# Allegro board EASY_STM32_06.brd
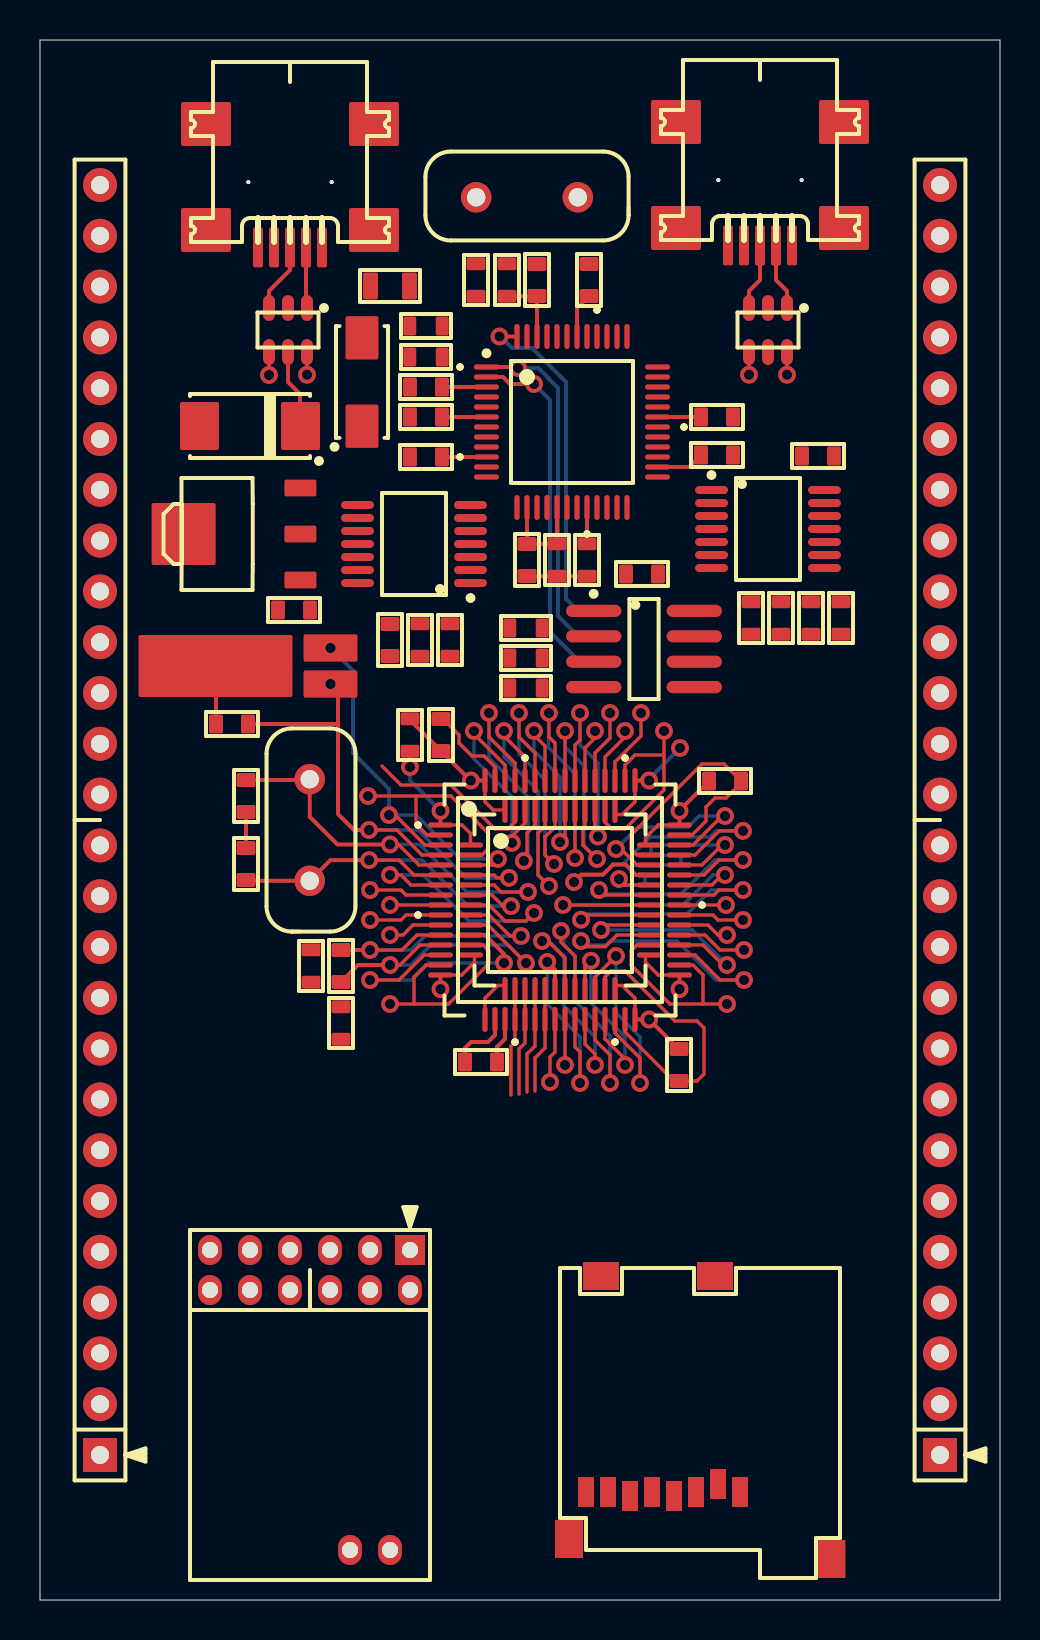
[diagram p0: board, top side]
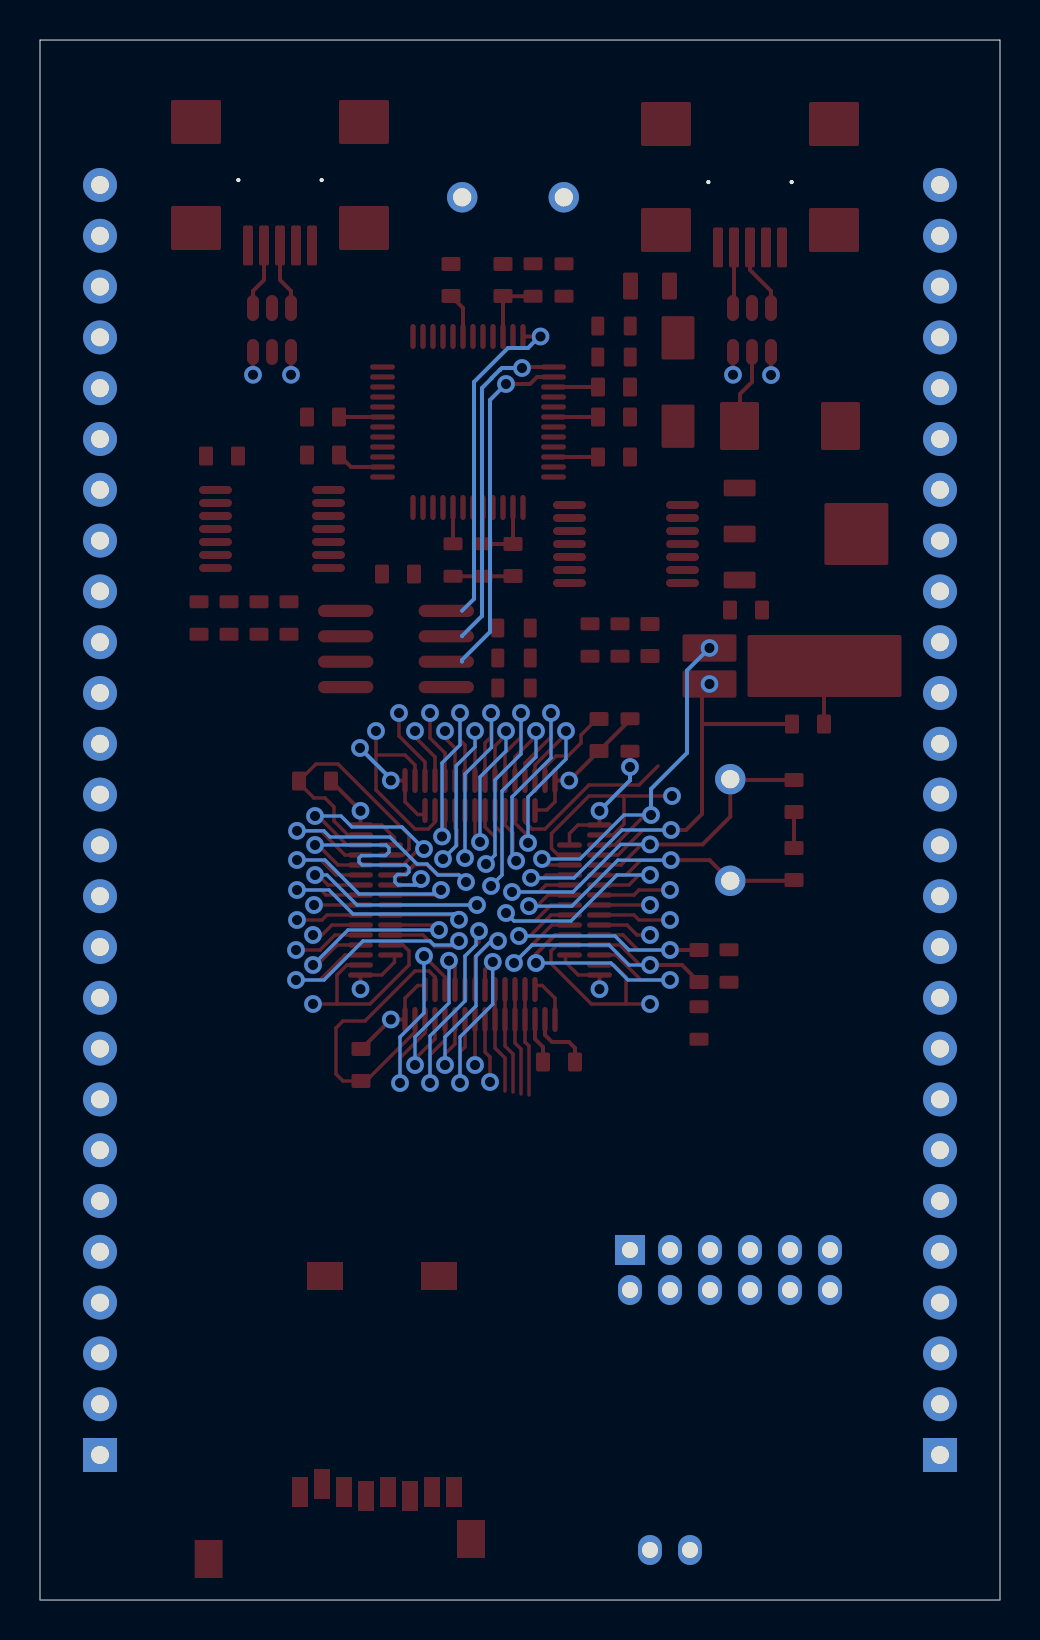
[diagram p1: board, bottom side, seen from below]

Outline 48 x 78 mm; copper layers: TOP, BOTTOM. Coordinates in mm from the lower left corner of the outline.
Outline path: 0,78 0,0 48,0 48,78 0,78

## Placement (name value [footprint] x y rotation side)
C1  22pF  [CAP0603_B]  10.3 40.2 270 top
C2  22p  [CAP0603_B]  10.3 36.8 90 top
C3  15p  [CAP0603_B]  9.6 43.8 180 top
C4  15p  [CAP0603_B]  12.7 49.5 180 top
C5  100n  [CAP0603_B]  15.05 31.7 90 top
C6  100n  [CAP0603_B]  31.95 26.75 270 top
C7  100n  [CAP0603_B]  34.25 40.95 0 top
C8  100n  [CAP0603_B]  20.05 43.25 90 top
C9  100n  [CAP0603_B]  22.05 26.9 180 top
C11  100n  [CAP0603_B]  19.3 60.65 180 top
C12  100n  [CAP0603_B]  27.45 66 90 top
C14  100n  [CAP0603_B]  19.3 57.15 180 top
C15  100n  [CAP0603_B]  24.35 52 270 top
C16  100n  [CAP0603_B]  33.85 57.25 0 top
C17  100n  [CAP0603_B]  33.85 59.15 0 top
C18  100n  [CAP0603_B]  24.85 66 90 top
C19  100n  [CAP0603_B]  19.3 59.15 180 top
C22  100n  [CAP0603_B]  30.1 51.3 180 top
C23  220uF  [CAP220UF]  10.5 58.7 180 top
C45  100nF  [CAP0603_B]  38.9 57.2 180 top
C46  100nF  [CAP0603_B]  17.5 48 270 top
D2  1N5819  [SS14]  16.1 60.9 90 top
J1  USB_MB  [HIROSE-US60-MB-5ST]  12.5 76.9 180 top
J2  USB_MB  [HIROSE-US60-MB-5ST]  36 77 180 top
L1  FB60R  [RES0805_B]  17.5 65.7 180 top
NOREF  -  [#3]  50 0 90 top
NOREF#2  -  [#3]  0 -2 0 top
R1  0R  [RES0603_B]  18.5 43.25 90 top
R2  0R  [RES0603_B]  15.05 28.85 270 top
R3  0R  [RES0603_B]  13.55 31.7 270 top
R4  470R  [RES0603_B]  23.35 66 270 top
R5  4K7  [RES0603_B]  19.3 63.7 0 top
R6  10K  [RES0603_B]  19.3 62.15 180 top
R7  10K  [RES0603_B]  27.35 52 270 top
R8  10K  [RES0603_B]  24.3 45.6 0 top
R9  10K  [RES0603_B]  24.3 47.1 0 top
R10  10K  [RES0603_B]  24.3 48.6 0 top
R13  1K5  [RES0603_B]  21.8 66 90 top
R14  100K  [RES0603_B]  25.85 52 270 top
R35  100R  [RES0603_B]  35.55 49.1 270 top
R36  100R  [RES0603_B]  40.05 49.1 270 top
R37  100R  [RES0603_B]  37.05 49.1 270 top
R38  100R  [RES0603_B]  38.55 49.1 270 top
R39  100K  [RES0603_B]  19 48 90 top
R40  100K  [RES0603_B]  20.5 48 90 top
REF  val  [unnamed]  18.5 17.5 180 top
REF#2  val  [unnamed#2]  45 7.25 90 top
U1  STM32F103RCT6  [LQFP64_MODIFIED]  26 35 0 top
U2  STM32F100  [LQFP48L_MODIFIED]  26 35 0 top
U3  FT2232D  [LQFP48L]  26.6 58.9 0 top
U4  AT93C46-10SI-2.7  [SOIC8S1JEDECM]  30.2 47.55 270 top
U5  74LVC125A  [TSOP65P640X120-14]  36.4 53.55 270 top
U6  74LVC125A  [TSOP65P640X120-14]  18.7 52.8 90 top
U7  LD1117-3V3  [SOT-223]  9.82 53.3 90 top
U10  MICRO_SD  [MICRO_SD_PUSH]  40 16.6 180 top
U11  USBLC6-2P6  [SOT23-6L]  36.4 63.5 180 top
U12  USBLC6-2P6  [SOT23-6L]  12.4 63.5 180 top
UNK*  val  [unnamed#2]  3 7.25 90 top
Y1  8M  [XTAL_DIP]  13.49 35.96 90 top
Y2  32.768KHz  [RTC-CRYSTAL]  10.53 46.7 90 top
Y3  6M  [XTAL_DIP]  26.89 70.14 180 top

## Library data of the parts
C1-C9 = C1005_0: User Part Number: pn; Tolerance: RichardLC
C11 C12 C14-C19 C22 = CAP NP_0: User Part Number: pn; Tolerance: RichardLC
C23 = CAPACITOR POL: User Part Number: pn; Tolerance: RichardLC
C45 C46 = C1005_5: User Part Number: pn; Tolerance: RichardLC
D2 = DIODE SCHOTTKY_1: User Part Number: pn; Tolerance: RichardLC
J1 J2 = CON9_2: User Part Number: pn; Tolerance: RichardLC
L1 = INDUCTOR/SM_0: User Part Number: pn; Tolerance: RichardLC
R1-R10 R13 R14 R35-R40 = R_0: User Part Number: pn; Tolerance: RichardLC
REF REF#2 = -: User Part Number: pn; Tolerance: RichardLC
U1 = STM32F103RCT6_2: User Part Number: pn; Tolerance: RichardLC
U2 = STM32F100_1: User Part Number: pn; Tolerance: RichardLC
U3 = FT2232D_0: User Part Number: pn; Tolerance: RichardLC
U4 = 93C46_2: User Part Number: pn; Tolerance: RichardLC
U5 U6 = 74HC125/LCC_0: User Part Number: pn; Tolerance: RichardLC
U7 = LD1117: User Part Number: pn; Tolerance: RichardLC
U10 = MOLEX_uSD_0: User Part Number: pn; Tolerance: RichardLC
U11 U12 = USBLC6-2P6: User Part Number: pn; Tolerance: RichardLC
UNK* = -: Tolerance: RichardLC; User Part Number: pn
Y1 Y3 = ZTB: Tolerance: ***; User Part Number: ***
Y2 = ZTA_0: User Part Number: pn; Tolerance: RichardLC

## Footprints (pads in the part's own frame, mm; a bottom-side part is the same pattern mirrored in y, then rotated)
CAP220UF
  custom 0.487x0.487 smd: 1(-2.525,0) 2(2.525,0)
CAP0603_B
  custom 0.175x0.175 smd: 1(-0.8,0) 2(0.8,0)
HIROSE-US60-MB-5ST
  round 0.2 hole 0.9 unplated: (-2.083,6.005) (2.083,6.005)
  custom 0.125x0.125 smd: 1(-1.6,9.271) 2(-0.8,9.271) 3(0,9.271) 4(0.8,9.271) 5(1.6,9.271)
  custom 0.55x0.55 smd: 6(-4.2,3.1) 7(4.2,3.1) 8(-4.2,8.4) 9(4.2,8.4)
LQFP48L
  oval 1.25x0.27 smd: 1(-4.275,2.75) 2(-4.275,2.25) 3(-4.275,1.75) 4(-4.275,1.25) 5(-4.275,0.75) 6(-4.275,0.25) 7(-4.275,-0.25) 8(-4.275,-0.75) 9(-4.275,-1.25) 10(-4.275,-1.75) 11(-4.275,-2.25) 12(-4.275,-2.75) 25(4.275,-2.75) 26(4.275,-2.25) 27(4.275,-1.75) 28(4.275,-1.25) 29(4.275,-0.75) 30(4.275,-0.25) 31(4.275,0.25) 32(4.275,0.75) 33(4.275,1.25) 34(4.275,1.75) 35(4.275,2.25) 36(4.275,2.75)
  oval 0.27x1.25 smd: 13(-2.75,-4.275) 14(-2.25,-4.275) 15(-1.75,-4.275) 16(-1.25,-4.275) 17(-0.75,-4.275) 18(-0.25,-4.275) 19(0.25,-4.275) 20(0.75,-4.275) 21(1.25,-4.275) 22(1.75,-4.275) 23(2.25,-4.275) 24(2.75,-4.275) 37(2.75,4.275) 38(2.25,4.275) 39(1.75,4.275) 40(1.25,4.275) 41(0.75,4.275) 42(0.25,4.275) 43(-0.25,4.275) 44(-0.75,4.275) 45(-1.25,4.275) 46(-1.75,4.275) 47(-2.25,4.275) 48(-2.75,4.275)
LQFP48L_MODIFIED
  oval 1.25x0.27 smd: 1(-4.475,2.75) 2(-4.475,2.25) 3(-4.475,1.75) 4(-4.475,1.25) 5(-4.475,0.75) 6(-4.475,0.25) 7(-4.475,-0.25) 8(-4.475,-0.75) 9(-4.475,-1.25) 10(-4.475,-1.75) 11(-4.475,-2.25) 12(-4.475,-2.75) 25(4.475,-2.75) 26(4.475,-2.25) 27(4.475,-1.75) 28(4.475,-1.25) 29(4.475,-0.75) 30(4.475,-0.25) 31(4.475,0.25) 32(4.475,0.75) 33(4.475,1.25) 34(4.475,1.75) 35(4.475,2.25) 36(4.475,2.75)
  oval 0.27x1.25 smd: 13(-2.75,-4.475) 14(-2.25,-4.475) 15(-1.75,-4.475) 16(-1.25,-4.475) 17(-0.75,-4.475) 18(-0.25,-4.475) 19(0.25,-4.475) 20(0.75,-4.475) 21(1.25,-4.475) 22(1.75,-4.475) 23(2.25,-4.475) 24(2.75,-4.475) 37(2.75,4.475) 38(2.25,4.475) 39(1.75,4.475) 40(1.25,4.475) 41(0.75,4.475) 42(0.25,4.475) 43(-0.25,4.475) 44(-0.75,4.475) 45(-1.25,4.475) 46(-1.75,4.475) 47(-2.25,4.475) 48(-2.75,4.475)
LQFP64_MODIFIED
  oval 1.25x0.27 smd: 1(-5.975,3.75) 2(-5.975,3.25) 3(-5.975,2.75) 4(-5.975,2.25) 5(-5.975,1.75) 6(-5.975,1.25) 7(-5.975,0.75) 8(-5.975,0.25) 9(-5.975,-0.25) 10(-5.975,-0.75) 11(-5.975,-1.25) 12(-5.975,-1.75) 13(-5.975,-2.25) 14(-5.975,-2.75) 15(-5.975,-3.25) 16(-5.975,-3.75) 33(5.975,-3.75) 34(5.975,-3.25) 35(5.975,-2.75) 36(5.975,-2.25) 37(5.975,-1.75) 38(5.975,-1.25) 39(5.975,-0.75) 40(5.975,-0.25) 41(5.975,0.25) 42(5.975,0.75) 43(5.975,1.25) 44(5.975,1.75) 45(5.975,2.25) 46(5.975,2.75) 47(5.975,3.25) 48(5.975,3.75)
  oval 0.27x1.25 smd: 17(-3.75,-5.975) 18(-3.25,-5.975) 19(-2.75,-5.975) 20(-2.25,-5.975) 21(-1.75,-5.975) 22(-1.25,-5.975) 23(-0.75,-5.975) 24(-0.25,-5.975) 25(0.25,-5.975) 26(0.75,-5.975) 27(1.25,-5.975) 28(1.75,-5.975) 29(2.25,-5.975) 30(2.75,-5.975) 31(3.25,-5.975) 32(3.75,-5.975) 49(3.75,5.975) 50(3.25,5.975) 51(2.75,5.975) 52(2.25,5.975) 53(1.75,5.975) 54(1.25,5.975) 55(0.75,5.975) 56(0.25,5.975) 57(-0.25,5.975) 58(-0.75,5.975) 59(-1.25,5.975) 60(-1.75,5.975) 61(-2.25,5.975) 62(-2.75,5.975) 63(-3.25,5.975) 64(-3.75,5.975)
MICRO_SD_PUSH
  rect 0.8x1.5 smd: 1(5,11.2) 2(6.1,10.8) 3(7.2,11.2) 4(8.3,11.4) 5(9.4,11.2) 6(10.5,11.4) 7(11.6,11.2) 8(12.7,11.2)
  rect 1.4x1.9 smd: G1(0.43,14.55) G2(13.55,13.55)
  rect 1.8x1.4 smd: S1(6.25,0.4) S2(11.95,0.4)
RES0603_B
  custom 0.163x0.163 smd: 1(-0.812,0) 2(0.812,0)
RES0805_B
  custom 0.188x0.188 smd: 1(-0.975,0) 2(0.975,0)
RTC-CRYSTAL
  custom 0.343x0.343 smd: 1(-0.9,-4) 2(0.9,-4)
  custom 0.775x0.775 smd: 3(0,1.75)
SOIC8S1JEDECM
  oval 0.61x2.77 smd: 1(-1.905,-2.515) 2(-0.635,-2.515) 3(0.635,-2.515) 4(1.905,-2.515) 5(1.905,2.515) 6(0.635,2.515) 7(-0.635,2.515) 8(-1.905,2.515)
SOT23-6L
  oval 0.6x1.3 smd: 1(-0.95,-1.1) 2(0,-1.1) 3(0.95,-1.1) 4(0.95,1.1) 5(0,1.1) 6(-0.95,1.1)
SOT-223
  custom 0.21x0.21 smd: 1(-2.3,-3.195) 2(0,-3.195) 3(2.3,-3.195)
  custom 0.775x0.775 smd: 4(0,2.645)
SS14
  custom 0.412x0.412 smd: A(2.21,0) C(-2.21,0)
TSOP65P640X120-14
  oval 0.4x1.65 smd: 1(-1.95,-2.825) 2(-1.3,-2.825) 3(-0.65,-2.825) 4(0,-2.825) 5(0.65,-2.825) 6(1.3,-2.825) 7(1.95,-2.825) 8(1.95,2.825) 9(1.3,2.825) 10(0.65,2.825) 11(0,2.825) 12(-0.65,2.825) 13(-1.3,2.825) 14(-1.95,2.825)
unnamed
  rect 1.5x1.5 hole 0.8: 1(0,0)
  oval 1.194x1.499 hole 0.8: 2(0,2) 3(2,0) 4(2,2) 5(4,0) 6(4,2) 7(6,0) 8(6,2) 9(8,0) 10(8,2) 11(10,0) 12(10,2) 13(1,15) 14(3,15)
unnamed#2
  rect 1.7x1.7 hole 0.9: 1(0,0)
  round 1.7 hole 0.9: 2(2.54,0) 3(5.08,0) 4(7.62,0) 5(10.16,0) 6(12.7,0) 7(15.24,0) 8(17.78,0) 9(20.32,0) 10(22.86,0) 11(25.4,0) 12(27.94,0) 13(30.48,0) 14(33.02,0) 15(35.56,0) 16(38.1,0) 17(40.64,0) 18(43.18,0) 19(45.72,0) 20(48.26,0) 21(50.8,0) 22(53.34,0) 23(55.88,0) 24(58.42,0) 25(60.96,0) 26(63.5,0)
XTAL_DIP
  round 1.524 hole 0.914: 1(0,0) 2(5.08,0)

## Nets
+3V3: C6.1 C7.1 C8.1 C9.1 C14.1 C15.1 C16.1 C17.1 C45.1 C46.1 R1.2 R2.2 R14.1 R39.1 R40.1 U1.19(VDD_4) U1.32(VDD_1) U1.48(VDD_2) U1.64(VDD_3) U2.24(VDD_1) U2.36(VDD_2) U2.48(VDD_3) U3.10(SI/WUA) U3.14(VCCIOA) U3.17(ADBUS6) U3.26(SI/WUB) U3.31(VCCIOB) U5.14(VCC) U6.14(VCC) U7.2(VOUT) U7.4(SH) U10.4(VDD)
+5V: C11.1 C12.1 C22.1 C23.1 D2.C R4.1 R8.1 R9.1 R10.1 U3.3(VCC1) U3.42(VCC2) U4.8(VCC) U7.3(VIN) U11.5(VBUS) U12.5(VBUS)
GND: C1.2 C2.2 C3.2 C4.2 C6.2 C7.2 C8.2 C9.2 C11.2 C12.2 C14.2 C15.2 C16.2 C17.2 C18.2 C19.2 C22.2 C23.2 C45.2 C46.2 J1.5(GND) J1.6(SH1) J1.7(SH2) J1.8(SH3) J1.9(SH4) J2.5(GND) J2.6(SH1) J2.7(SH2) J2.8(SH3) J2.9(SH4) R3.2 R6.2 R7.2 R14.2 U1.18(VSS_4) U1.31(VSS_1) U1.47(VSS_2) U1.63(VSS_3) U2.23(VSS_1) U2.35(VSS_2) U2.47(VSS_3) U3.9(GND1) U3.18(GND2) U3.25(GND3) U3.34(GND4) U3.45(AGND) U3.47(TEST) U4.5(GND) U4.7(NC) U5.7(GND) U6.1(O\E\1\) U6.2(A1) U6.7(GND) U6.9(A3) U6.10(O\E\3\) U7.1(GND) U10.6(VSS) U11.2(GND) U12.2(GND) Y2.3
VBAT: R1.1 U1.1(VBAT) U2.1(VBAT)
VDDA: C5.1 R2.1 U1.13(VDDA) U2.9(VDDA)
VSSA: C5.2 R3.1 U1.12(VSSA) U2.8(VSSA)
BOOT0: U1.60(BOOT0) U2.44(BOOT0)
EECK: R9.2 U3.1(EESK) U4.2(CLK)
EECS: R10.2 U3.48(EECS) U4.1(CS)
EEDA: R8.2 U3.2(EEDATA) U4.3(DI)
JT_SRSTN: U3.16(ADBUS7)
JTG_SELN: U5.1(O\E\1\) U5.4(O\E\2\) U5.10(O\E\3\) U5.13(O\E\4\)
NRST: U1.7(NRST) U2.7(NRST)
OSC32_IN: C4.1 U1.3(PC14/OSC32_IN) U2.3(PC14/OSC32_IN) Y2.2
OSC32_OUT: C3.1 U1.4(PC15/OSC32/OUT) U2.4(PC15/OSC32_OUT) Y2.1
OSC_IN: C1.1 U1.5(PD0/OSC_IN) U2.5(PD0/OSC_IN) Y1.2
OSC_OUT: C2.1 U1.6(PD1/OSC_OUT) U2.6(PD1/OSC_OUT) Y1.1
PA0: U1.14(PA0-WKUP) U2.10(PA0/WKUP)
PA1: U1.15(PA1) U2.11(PA1)
PA2: U1.16(PA2) U2.12(PA2)
PA3: U1.17(PA3) U2.13(PA3)
PA4: U1.20(PA4) U2.14(PA4)
PA5: U1.21(PA5) U2.15(PA5)
PA6: U1.22(PA6) U2.16(PA6)
PA7: U1.23(PA7) U2.17(PA7)
PA8: U1.41(PA8) U2.29(PA8)
PA9: U1.42(PA9) U2.30(PA9)
PA10: U1.43(PA10) U2.31(PA10)
PA11: U1.44(PA11) U2.32(PA11) U11.6(IO1_2)
PA12: U1.45(PA12) U2.33(PA12) U11.4(IO2_2)
PA13: R36.2 U1.46(PA13) U2.34(PA13)
PA14: R38.2 U1.49(PA14) U2.37(PA14)
PA15: R37.2 U1.50(PA15) U2.38(PA15)
PB0: U1.26(PB0) U2.18(PB0)
PB1: U1.27(PB1) U2.19(PB1)
PB2: U1.28(PB2/BOOT1) U2.20(PB2)
PB3: R35.2 U1.55(PB3) U2.39(PB3)
PB4: U1.56(PB4) U2.40(PB4)
PB5: U1.57(PB5) U2.41(PB5)
PB6: U1.58(PB6) U2.42(PB6)
PB7: U1.59(PB7) U2.43(PB7)
PB8: U1.61(PB8) U2.45(PB8)
PB9: U1.62(PB9) U2.46(PB9)
PB10: U1.29(PB10) U2.21(PB10)
PB11: U1.30(PB11) U2.22(PB11)
PB12: U1.33(PB12) U2.25(PB12)
PB13: U1.34(PB13) U2.26(PB13)
PB14: U1.35(PB14) U2.27(PB14)
PB15: U1.36(PB15) U2.28(PB15)
PC0: U1.8(PC0)
PC1: U1.9(PC1)
PC2: U1.10(PC2)
PC3: U1.11(PC3)
PC4: U1.24(PC4)
PC5: U1.25(PC5)
PC6: U1.37(PC6)
PC7: U1.38(PC7)
PC8: U1.39(PC8)
PC9: U1.40(PC9)
PC10: U1.51(PC10)
PC11: U1.52(PC11)
PC12: U1.53(PC12)
PC13: U1.2(PC13/TAMPER/RTC) U2.2(PC13/TAMPER/RTC)
PD2: U1.54(PD2)
RXD: U3.39(BDBUS1)
SRST: U3.11(ACBUS3) U6.12(A4)
SRST_OE: R39.2 U3.12(ACBUS2) U6.13(O\E\4\)
TRST: U3.13(ACBUS1) U6.5(A2)
TRST_OE: R40.2 U3.15(ACBUS0) U6.4(O\E\2\)
TXD: U3.40(BDBUS0)
USB_CLK: U3.24(ADBUS0) U5.12(A4)
USB_TDI: U3.23(ADBUS1) U5.9(A3)
USB_TDO: U3.22(ADBUS2) U5.2(A1)
USB_TMS: U3.21(ADBUS3) U5.5(A2)
N50123: R13.1 U3.7(USBDP) U12.4(IO2_2)
N50127: C18.1 R4.2 U3.46(AVCC)
N50535: R7.1 U3.20(ADBUS4)
N50793: U3.43(XTIN) Y3.1
N50801: U3.44(XTOUT) Y3.2
N51029: D2.A L1.1 R5.1
N51243: J1.1(VBUS) L1.2
N51319: R13.2 U3.5(R\S\T\O\U\T\)
N51343: U3.8(USBDM) U12.6(IO1_2)
N51347: R5.2 R6.1 U3.4(R\E\S\E\T\)
N51363: C19.1 U3.6(3V3OUT)
N51511: U4.4(DO)
N70187: U10.7(DAT0/DO)
N70219: U10.5(CLK)
N70227: U10.2(CD/C\S\/DAT3)
N70305: U10.S2
N70345: U10.G2
N70603: U10.8(DAT1/RSV)
N14914218: U10.3(CMD/DI)
N14919452: R35.1 U5.3(Y1)
N14919456: R36.1 U5.6(Y2)
N14919460: R37.1 U5.8(Y3)
N14919464: R38.1 U5.11(Y4)
N14919761: U10.1(DAT2/NC)
N14928576: U6.6(Y2)
N14928580: U6.11(Y4)
N14948550: J2.1(VBUS)
N14948554: J2.2(DM) U11.1(IO1_1)
N14948558: J2.3(DP) U11.3(IO2_1)
N14959571: J1.3(DP) U12.3(IO2_1)
N14961045: J1.2(DM) U12.1(IO1_1)

Pads without a net: J1 4; J2 4; REF 1 2 3 4 5 6 7 8 9 10 11 12 13 14; REF#2 1 2 3 4 5 6 7 8 9 10 11 12 13 14 15 16 17 18 19 20 21 22 23 24 25 26; U3 19 27 28 29 30 32 33 35 36 37 38 41; U4 6; U6 3 8; U10 G1 S1; UNK* 1 2 3 4 5 6 7 8 9 10 11 12 13 14 15 16 17 18 19 20 21 22 23 24 25 26

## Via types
v1: diameter 0.889, hole 0.508, TOP to BOTTOM, 94 vias

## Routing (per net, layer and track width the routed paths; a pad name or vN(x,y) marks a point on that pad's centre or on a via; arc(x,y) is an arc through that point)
+3V3: length 31.8
  TOP w0.175: 28.75,30.73 29.11,30.73 29.75,30.09 U1.32 ; U1.48 30.91,38.75 30.27,38.11 30.27,37.75 ; U1.64 22.25,39.91 22.66,39.5 23.25,39.5
  TOP w0.2: U1.19 23.25,28.05 22.85,27.65 C9.1 ; C17.1 U3.31 ; U3.26 32.45,56.65 C16.1 ; U1.64 v1(21.54,40.98) 21.52,40.98 C8.1 18.5,44 R1.2 ; U3.14 C15.1 25.84,52.8 R14.1 U3.17 ; 31.93,27.55 v1(30.46,29.02) U1.32 ; C7.1 31.98,39.48 v1(31.98,39.46) U1.48 ; U3.10 C14.1
+5V: length 8.5
  TOP w0.2: 26.85,63.17 26.85,64.6 C12.1 ; C11.1 U3.3 ; U12.5 12.4,60.9 13,60.3 13,58.73 C23.1
GND: length 52.7
  TOP w0.175: C8.2 20.15,44.05 20.95,43.25 20.95,42.85 21.6,42.2 22.2,42.2 22.75,41.65 U1.63 ; 28.25,30.73 28.25,31.15 28.55,31.45 29.25,31.45 31.75,28.95 32.85,28.95 33.2,28.6 33.2,26.3 32.85,25.95 C6.2 31.7,25.95 29.25,28.4 U1.31 ; U2.35 29.85,37.25 29.55,37.55 29.55,38.25 33.1,41.8 34.2,41.8 C7.2 35.05,40.85 34.3,40.1 33.75,40.1 33.3,39.65 33.3,38.95 32.6,38.25 U1.47 ; 17.1,41.7 18.05,40.75 20.55,40.75 22.75,38.55 23.4,38.55 23.75,38.9 U2.47
  TOP w0.2: R7.2 R14.2 24.36,51.19 C15.2 ; Y2.3 8.8,46.67 C3.2 ; C9.2 21.25,27.6 21.55,27.9 22.4,27.9 22.75,28.25 U1.18 ; C2.2 C1.2
VBAT: length 6.6
  TOP w0.175: U1.1 21.1,38.75 21.52,38.33 U2.1
  TOP w0.2: R1.1 v1(18.5,41.65) ; U1.1 v1(20.02,39.46)
  BOTTOM w0.2: v1(20.02,39.46) 18.5,40.98 v1(18.5,41.65)
VDDA: length 16.9
  TOP w0.175: v1(17.5,31.75) 18,31.75 19,32.75 U1.13 ; v1(24.3,31.85) 22.4,33.75 U2.9
  TOP w0.2: v1(17.5,31.75) 15.9,31.75 C5.1
  BOTTOM w0.175: v1(24.3,31.85) 23.4,32.75 19.55,32.75 18.55,31.75 v1(17.5,31.75)
VSSA: length 16.1
  TOP w0.175: U1.12 18.85,33.25 18.1,32.5 v1(16.5,32.5) ; U2.8 22.45,34.25 23.5,33.2 v1(24.05,33.2)
  TOP w0.2: v1(16.5,32.5) C5.2
  BOTTOM w0.175: v1(24.05,33.2) 19.25,33.2 18.55,32.5 v1(16.5,32.5)
BOOT0: length 15.7
  TOP w0.175: U2.44 25.25,38.7 24.9,38.35 24.9,36.25 v1(25.45,35.7) ; U1.60 24.25,42.15 23.2,43.2 v1(23.2,43.45)
  BOTTOM w0.175: v1(23.2,43.45) 23.2,42.15 24.9,40.45 24.9,36.25 v1(25.45,35.7)
EECK: length 16.8
  TOP w0.2: U3.1 23.85,61.65 v1(23.9,61.6)
  BOTTOM w0.2: v1(23.9,61.6) 24.9,61.6 24.98,61.52 25,61.52 25.42,61.1 25.42,61.08 25.9,60.6 25.9,49.2 26.9,48.2 26.9,48.19
EECS: length 16.8
  TOP w0.2: 23.85,63.17 v1(22.98,63.17)
  BOTTOM w0.2: 26.9,49.45 26.3,50.05 26.3,60.9 24.6,62.6 23.6,62.6 23.02,63.17 v1(22.98,63.17)
EEDA: length 17.3
  TOP w0.2: U3.2 23.15,61.15 23.5,60.8 v1(24.7,60.8)
  BOTTOM w0.2: v1(24.7,60.8) 25.5,60 25.5,48.4 26.9,47 26.9,46.91
NRST: length 14.7
  TOP w0.175: v1(17.5,36.25) 18.05,36.25 18.55,35.75 U1.7 ; U2.7 22.45,34.75 23.25,33.95 24.3,33.95 v1(24.7,34.35)
  BOTTOM w0.175: v1(17.5,36.25) 19.15,36.25 21.45,33.95 24.3,33.95 v1(24.7,34.35)
OSC32_IN: length 20.6
  TOP w0.175: U1.3 19.25,37.75 17.75,39.25 v1(17.45,39.25) ; v1(22.9,37.05) 22.6,36.75 U2.3
  BOTTOM w0.175: v1(22.9,37.05) 21,37.05 18.8,39.25 v1(17.45,39.25)
  BOTTOM w0.2: v1(17.45,39.25) 17.45,40.55 15.65,42.35 15.65,46.48 v1(14.53,47.6)
OSC32_OUT: length 27.1
  TOP w0.175: v1(23.45,36.11) 22.84,36.11 22.7,36.25 U2.4 ; v1(16.45,38.5) 17.85,38.5 19.1,37.25 U1.4
  TOP w0.2: v1(16.45,38.5) 15.7,38.5 14.9,39.3 14.9,43.8 ; 14.9,43.8 C3.1 ; 14.9,43.8 14.9,45.42 v1(14.53,45.8)
  BOTTOM w0.175: v1(23.45,36.11) 23.44,36.1 21.3,36.1 18.9,38.5 v1(16.45,38.5)
OSC_IN: length 23.5
  TOP w0.175: v1(17.5,37.78) 17.92,37.78 18.95,36.75 U1.5 ; v1(24.4,35.4) 23.05,35.4 22.7,35.75 U2.5
  TOP w0.2: C1.1 13.45,41 Y1.2 13.49,39.16 14.87,37.78 v1(17.5,37.78)
  BOTTOM w0.175: v1(24.4,35.4) 21.35,35.4 18.97,37.78 v1(17.5,37.78)
OSC_OUT: length 20.8
  TOP w0.175: U1.6 18.7,36.25 17.96,36.99 v1(16.46,36.99) ; U2.6 22.6,35.25 23.16,34.69 v1(23.55,34.69)
  TOP w0.2: v1(16.46,36.99) 14.52,36.99 Y1.1 10.34,35.96 C2.1
  BOTTOM w0.175: v1(16.46,36.99) 19.11,36.99 21.41,34.69 v1(23.55,34.69)
PA0: length 13.6
  TOP w0.175: v1(16.5,31) 17.95,31 19.2,32.25 U1.14
  TOP w0.2: U2.10 22.25,33.25 23.2,32.3 v1(23.2,31.85)
  BOTTOM w0.175: v1(23.2,31.85) 19.45,31.85 18.6,31 v1(16.5,31)
PA1: length 10.2
  TOP w0.175: 18.7,29.8 18.7,31.15 19.3,31.75 U1.15 ; 18.7,29.8 20.43,29.8 22.45,31.82 22.45,32.45 22.15,32.75 21.73,32.75 ; 18.7,29.8 v1(17.5,29.8)
PA2: length 3
  TOP w0.175: 21.73,32.25 21.73,31.89 21.09,31.25 U1.16
  TOP w0.2: U1.16 v1(20.02,30.54)
PA3: length 2.3
  TOP w0.175: 23.25,30.73 22.89,30.73 22.25,30.09 U1.17
PA4: length 5.6
  TOP w0.175: 23.55,25.25 23.55,27.7 23.75,27.9 U1.20 U2.14 23.75,30.73
PA5: length 5.5
  TOP w0.175: 24.25,30.73 U2.15 U1.21 24.25,27.85 23.95,27.55 23.95,25.3
PA6: length 5.5
  TOP w0.175: 24.75,30.73 U2.16 U1.22 24.75,27.7 24.35,27.3 24.35,25.4
PA7: length 5.5
  TOP w0.175: 25.25,30.73 U2.17 U1.23 25.25,27.6 24.75,27.1 24.75,25.45
PA8: length 15.5
  TOP w0.175: U1.41 33.7,35.25 33.95,35.5 v1(35.15,35.5) ; U2.29 27.3,34.25 27.06,34.01 v1(27.05,34.01)
  BOTTOM w0.175: v1(27.05,34.01) 27.34,34.3 32.35,34.3 33.55,35.5 v1(35.15,35.5)
PA9: length 15.5
  TOP w0.175: U1.42 33.6,35.75 34.1,36.25 v1(34.25,36.25) ; v1(26.15,34.75) U2.30
  BOTTOM w0.175: v1(34.25,36.25) 33.65,36.25 32.15,34.75 v1(26.15,34.75)
PA10: length 14.1
  TOP w0.175: U1.43 33.2,36.25 33.95,37 v1(35.15,37) ; v1(27.95,35.5) 28.05,35.5 28.3,35.25 U2.31
  BOTTOM w0.175: v1(27.95,35.5) 28.15,35.3 32.05,35.3 33.75,37 v1(35.15,37)
PA11: length 16.6
  TOP w0.175: U1.44 33.1,36.75 34.1,37.75 v1(34.25,37.75) ; v1(28.95,36.05) 29.25,35.75 U2.32
  TOP w0.2: U11.6 v1(37.35,61.26)
  BOTTOM w0.175: v1(28.95,36.05) 29.25,35.75 30.1,35.75 30.25,35.9 30.25,36.15 30.12,36.27 29.68,36.27 29.55,36.4 29.55,36.6 29.7,36.75 31.9,36.75 32.05,36.9 32.05,37.1 31.93,37.23 30.73,37.23 30.55,37.4 30.55,37.6 30.7,37.75 v1(34.25,37.75)
PA12: length 18.7
  TOP w0.175: v1(35.15,38.46) 33.96,38.46 32.75,37.25 U1.45
  TOP w0.2: U11.4 v1(35.45,61.26) ; U2.33 29.8,36.25 29.28,36.77 28.65,36.77 28.15,36.27 27.07,36.27 v1(26.7,35.9)
  BOTTOM w0.175: v1(35.15,38.46) 33.81,38.46 33.5,38.15 30.5,38.15 29.15,36.8 28.65,36.8 28.1,36.25 27.05,36.25 v1(26.7,35.9)
PA13: length 11
  TOP w0.175: v1(34.25,39.2) 34.1,39.2 32.65,37.75 U1.46 ; U2.34 29.85,36.75 29.05,37.55 v1(28.8,37.55)
  BOTTOM w0.175: v1(34.25,39.2) 32.95,39.2 32.4,38.65 29.9,38.65 v1(28.8,37.55)
PA14: length 5.3
  TOP w0.175: 28.75,39.27 29.11,39.27 29.75,39.91 U1.49
  TOP w0.2: U1.49 v1(30.46,40.98)
  BOTTOM w0.2: v1(32,42.6) 30.46,41.06 v1(30.46,40.98)
PA15: length 10.4
  TOP w0.175: U1.50 29.25,41.75 29.75,42.25 31.2,42.25 ; 31.2,42.25 v1(31.2,43.45) ; 31.2,42.25 31.2,40.5 29.25,38.55 28.59,38.55 28.25,38.89 U2.38
PB0: length 11.5
  TOP w0.175: U1.26 26.75,27.65 27,27.4 v1(27,25.85)
  TOP w0.2: v1(25.36,31.9) 25.75,31.52 U2.18
  BOTTOM w0.175: v1(27,25.85) 27,28.15 25.36,29.79 v1(25.36,31.9)
PB1: length 13.1
  TOP w0.175: U1.27 27.25,27.8 27.75,27.3 v1(27.75,26.75) ; v1(25.1,32.95) 25.4,32.95 26.25,32.1 U2.19
  BOTTOM w0.175: v1(27.75,26.75) 27.75,28.15 26.2,29.7 26.2,32.2 25.45,32.95 v1(25.1,32.95)
PB2: length 15.3
  TOP w0.175: v1(26.05,33.45) 26.05,32.89 26.75,32.19 U2.20 ; v1(28.5,25.85) 28.5,27.25 27.75,28 U1.28
  BOTTOM w0.175: v1(28.5,25.85) 28.5,28.2 26.75,29.95 26.75,32.2 26.2,32.75 26.2,33.3 v1(26.05,33.45)
PB3: length 11.4
  TOP w0.175: v1(27,44.35) 27,43 26.75,42.75 U1.55
  TOP w0.2: v1(27.9,38.17) 27.75,38.33 U2.39
  BOTTOM w0.175: v1(27,44.35) 27,42.75 27.9,41.85 v1(27.9,38.17)
PB4: length 12.3
  TOP w0.175: U2.40 27.25,38.6 27.15,38.5 27.15,37.75 v1(27.85,37.05) ; U1.56 v1(26.25,43.45)
  BOTTOM w0.175: v1(27.85,37.05) 27.19,37.71 27.19,41.71 26.25,42.65 v1(26.25,43.45)
PB5: length 13.7
  TOP w0.175: U1.57 25.75,42.85 25.45,43.15 v1(25.45,44.35) ; U2.41 v1(26.75,37.1)
  BOTTOM w0.175: v1(25.45,44.35) 25.43,44.33 25.43,42.62 26.75,41.3 v1(26.75,37.1)
PB6: length 10.5
  TOP w0.175: U2.42 26.25,38.15 v1(26,37.9) ; v1(24.7,43.45) 24.7,43.25 25.25,42.7 U1.58
  BOTTOM w0.175: v1(26,37.9) 26,41.15 24.7,42.45 v1(24.7,43.45)
PB7: length 15
  TOP w0.175: v1(25.7,36.8) 25.25,37.25 25.25,38.15 25.75,38.65 U2.43 ; U1.59 24.75,42.35 23.95,43.15 v1(23.95,44.35)
  BOTTOM w0.175: v1(23.95,44.35) 23.95,42.3 25.25,41 25.25,37.25 v1(25.7,36.8)
PB8: length 15
  TOP w0.175: v1(22.45,44.35) 22.45,43.15 23.75,41.85 U1.61 ; U2.45 24.75,38.75 24.35,38.35 24.35,37.11 v1(24.19,36.95)
  BOTTOM w0.175: v1(24.19,36.95) 24.4,37.16 24.4,40.15 22.45,42.1 v1(22.45,44.35)
PB9: length 11.4
  TOP w0.175: U2.46 24.25,38.85 23.6,38.2 v1(23.6,37.85) ; v1(21.7,43.45) 21.7,43.3 23.25,41.75 U1.62
  BOTTOM w0.175: v1(23.6,37.85) 23.6,40.15 21.7,42.05 v1(21.7,43.45)
PB10: length 10.2
  TOP w0.175: v1(27.55,31.96) 27.25,31.66 U2.21 ; U1.29 28.25,28.05 29.25,27.05 v1(29.25,26.75)
  BOTTOM w0.175: v1(27.55,31.96) 27.55,29.85 29.25,28.15 v1(29.25,26.75)
PB11: length 12.6
  TOP w0.175: v1(28.8,32.2) 27.75,31.15 U2.22 ; U1.30 28.75,28.35 30,27.1 v1(30,25.85)
  BOTTOM w0.175: v1(30,25.85) 30,28.15 28.8,29.35 v1(28.8,32.2)
PB12: length 3
  TOP w0.175: 30.27,32.25 30.27,31.89 30.91,31.25 U1.33
  TOP w0.2: U1.33 v1(31.98,30.54)
PB13: length 10
  TOP w0.175: v1(34.35,29.8) 33.15,29.8 ; 33.15,29.8 33.15,31.25 32.65,31.75 U1.34 ; 33.15,29.8 31.5,29.8 29.55,31.75 29.55,32.45 29.85,32.75 30.27,32.75
PB14: length 16.6
  TOP w0.175: U1.35 32.75,32.25 34,31 v1(35.2,31) ; v1(27.05,32.95) 27.33,32.67 28.27,32.67 28.85,33.25 U2.27
  BOTTOM w0.175: v1(27.05,32.95) 27.25,32.75 28.3,32.75 28.5,32.95 31.85,32.95 33.8,31 v1(35.2,31)
PB15: length 12.3
  TOP w0.175: U2.28 28.3,33.75 v1(28.05,33.5) ; v1(34.35,31.75) 34.15,31.75 33.15,32.75 U1.36
  BOTTOM w0.175: v1(34.35,31.75) 32.6,33.5 v1(28.05,33.5)
PC0: length 3.6
  TOP w0.175: v1(16.5,35.5) 18.05,35.5 18.3,35.25 U1.8
PC1: length 2.5
  TOP w0.175: U1.9 v1(17.5,34.75)
PC2: length 3.6
  TOP w0.175: U1.10 18.3,34.25 18.05,34 v1(16.5,34)
PC3: length 2.7
  TOP w0.175: v1(17.5,33.25) 18.15,33.25 18.65,33.75 U1.11
PC4: length 3.2
  TOP w0.175: v1(25.5,25.9) 25.5,27.15 25.75,27.4 U1.24
PC5: length 2.3
  TOP w0.175: U1.25 v1(26.25,26.75)
PC6: length 3.5
  TOP w0.175: U1.37 33.25,33.25 34,32.5 v1(35.2,32.5)
PC7: length 2.6
  TOP w0.175: v1(34.35,33.25) 33.9,33.25 33.4,33.75 U1.38
PC8: length 3.3
  TOP w0.175: v1(35.15,34) 33.9,34 33.65,34.25 U1.39
PC9: length 2.3
  TOP w0.175: U1.40 v1(34.3,34.75)
PC10: length 3.9
  TOP w0.175: v1(30.05,44.35) 30.05,43.2 28.75,41.9 U1.51
PC11: length 2.9
  TOP w0.175: v1(29.25,43.45) 29.25,43.15 28.25,42.15 U1.52
PC12: length 3.7
  TOP w0.175: U1.53 27.75,42.35 28.5,43.1 v1(28.5,44.35)
PC13: length 11.4
  TOP w0.175: 18.8,40.2 20.55,40.2 22.43,38.33 22.43,37.58 22.1,37.25 U2.2 ; 18.8,40.2 v1(16.4,40.2) ; 18.8,40.2 18.8,38.8 19.35,38.25 U1.2
PD2: length 2.7
  TOP w0.175: U1.54 27.25,42.6 27.75,43.1 v1(27.75,43.45)
N50123: length 1.1
  TOP w0.2: U12.4 v1(11.45,61.25)
N50127: length 3.5
  TOP w0.2: R4.2 24.84,65.19 C18.1 24.85,63.17
N50535: length 1.8
  TOP w0.2: R7.1 U3.20
N51343: length 1.1
  TOP w0.2: U12.6 v1(13.35,61.26)
N51363: length 2.2
  TOP w0.2: C19.1 U3.6
N14948554: length 3.4
  TOP w0.2: U11.1 37.35,65.45 36.8,66 J2.2
N14948558: length 3.4
  TOP w0.2: J2.3 36,66 35.45,65.45 U11.3
N14959571: length 3.5
  TOP w0.2: U12.3 11.45,65.45 12.5,66.5 J1.3
N14961045: length 3
  TOP w0.2: U12.1 13.3,64.65 J1.2

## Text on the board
DIMENSION: FIGURE | SIZE | 0.508 | 0.8 | 0.8999 | 0.9144 | 1.0 | 2.4 | DRILL CHART: TOP to BOTTOM | ALL UNITS ARE IN MILLIMETERS | PLATED | QTY | 121 | 14 | 200 | 2 | 4
